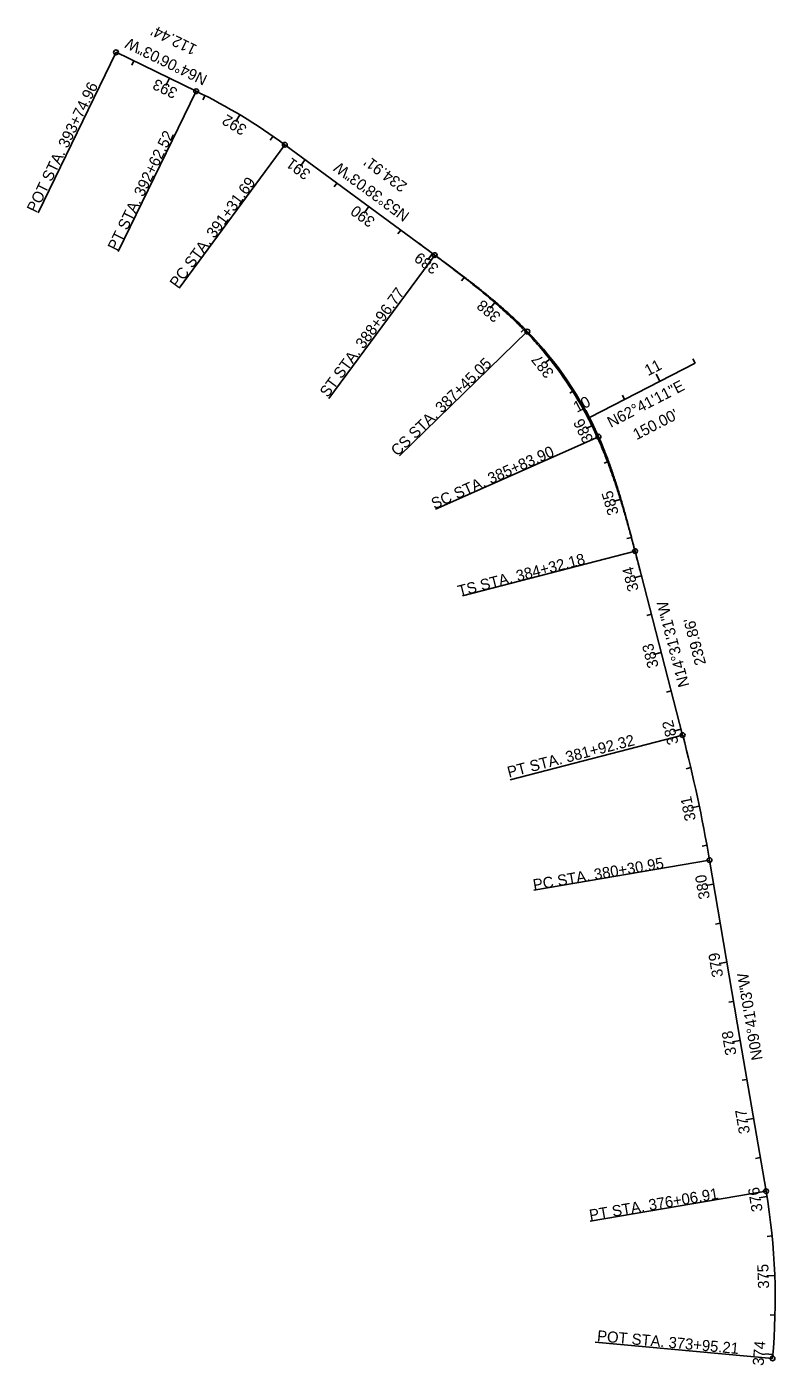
# Model space of a CAD drawing. Extents: x 111353 to 112297, y 429419 to 431109.
import ezdxf

# ---------------------------------------------------------------- set-up
doc = ezdxf.new("R2010")
doc.units = 0
for name, color, linetype in [('DR_P_Headwall', 7, 'Continuous'), ('DT_X_Island', 7, 'Continuous'), ('DT_X_Terrain_Boundary', 7, 'Continuous'), ('GK_Drainage_Nodes', 7, 'Continuous'), ('PV_P_Shoulder', 7, 'Continuous')]:
    doc.layers.add(name, color=color, linetype=linetype)

msp = doc.modelspace()

# ---------------------------------------------------------------- linework, layer by layer
at = {"layer": 'DR_P_Headwall'}
for p, q in [((111488, 431065.5), (111485.4, 431060.1)), ((111533, 431043.7), (111528.6, 431034.7)), ((111577.9, 431021.8), (111575.2, 431016.4)), ((111621.7, 430997.6), (111616.6, 430989)), ((111663.7, 430970.4), (111660.2, 430965.5)), ((111704.1, 430941), (111698.2, 430932.9)), ((111744.3, 430911.3), (111740.8, 430906.5)), ((111784.6, 430881.7), (111778.7, 430873.6)), ((111824.9, 430852), (111821.3, 430847.2)), ((111865.1, 430822.4), (111859.2, 430814.3)), ((111905.2, 430792.6), (111901.6, 430787.8)), ((111944.3, 430761.4), (111937.9, 430753.7)), ((111981.1, 430727.6), (111976.9, 430723.4)), ((112014.4, 430690.2), (112006.5, 430684)), ((112196.2, 430684.1), (112193.4, 430689.5)), ((112151.7, 430661.2), (112147.1, 430670.1)), ((112043.3, 430649.5), (112038.2, 430646.3)), ((112107.3, 430638.3), (112104.5, 430643.6)), ((112062.9, 430615.3), (112058.3, 430624.2)), ((112067.6, 430605.8), (112058.7, 430601.5)), ((112087.2, 430559.8), (112081.5, 430557.8)), ((112102.8, 430512.3), (112093.2, 430509.5)), ((112116, 430464.1), (112110.2, 430462.6)), ((112128.6, 430415.7), (112118.9, 430413.2)), ((112141.1, 430367.3), (112135.3, 430365.8)), ((112153.6, 430318.9), (112144, 430316.4)), ((112166.2, 430270.5), (112160.4, 430269)), ((112178.7, 430222.1), (112169, 430219.6)), ((112190.8, 430173.6), (112185, 430172.2)), ((112201.6, 430124.8), (112191.8, 430122.8)), ((112211.2, 430075.7), (112205.3, 430074.6)), ((112219.7, 430026.4), (112209.8, 430024.8)), ((112228.1, 429977.2), (112222.2, 429976.1)), ((112236.5, 429927.9), (112226.6, 429926.2)), ((112244.9, 429878.6), (112239, 429877.6)), ((112253.3, 429829.3), (112243.5, 429827.6)), ((112261.7, 429780), (112255.8, 429779)), ((112270.1, 429730.7), (112260.3, 429729)), ((112278.6, 429681.4), (112272.6, 429680.4)), ((112286.9, 429632.1), (112277.1, 429630.5)), ((112293.4, 429582.6), (112287.4, 429582)), ((112296.8, 429532.7), (112286.8, 429532.3)), ((112297.2, 429482.7), (112291.2, 429482.8)), ((112294.5, 429432.8), (112284.5, 429433.6))]:
    msp.add_line(p, q, dxfattribs=at)
at = {"layer": 'DT_X_Terrain_Boundary'}
for p, q in [((111465.6, 431076.4), (111367.3, 430874)), ((111566.7, 431027.3), (111468.5, 430824.9)), ((111678.6, 430959.8), (111545.2, 430778.6)), ((111867.7, 430820.5), (111734.3, 430639.3)), ((111984.6, 430724), (111823.2, 430567.3)), ((112074.4, 430591.3), (111868.9, 430499.7)), ((112120.5, 430446.9), (111902.7, 430390.4)), ((112180.6, 430214.7), (111962.8, 430158.3)), ((112214.5, 430056.9), (111992.7, 430019.1)), ((112285.8, 429639), (112064, 429601.1)), ((112294.1, 429428), (112070, 429448.4))]:
    msp.add_line(p, q, dxfattribs=at)
for centre in [(111465.6, 431076.4), (111566.7, 431027.3), (111678.6, 430959.8), (111867.7, 430820.5), (111984.6, 430724), (112074.4, 430591.3), (112120.5, 430446.9), (112180.6, 430214.7), (112214.5, 430056.9), (112285.8, 429639), (112294.1, 429428)]:
    msp.add_circle(centre, 3, dxfattribs=at)
at = {"layer": 'PV_P_Shoulder'}
for p, q in [((111566.7, 431027.3), (111465.6, 431076.4)), ((111867.7, 430820.5), (111678.6, 430959.8)), ((112062.9, 430615.3), (112196.2, 430684.1)), ((112180.6, 430214.7), (112120.5, 430446.9)), ((112253.3, 429829.3), (112214.5, 430056.9)), ((112285.8, 429639), (112253.3, 429829.3))]:
    msp.add_line(p, q, dxfattribs=at)
for centre, radius, start, end in [((111253.8, 430383), 716.3, 53.6341, 64.099), ((111655.7, 430404.8), 458.4, 24.0078, 44.1517), ((111655.7, 430404.8), 458.4, 24.0078, 44.1517), ((111654.3, 430403.8), 458.4, 27.0878, 41.0717), ((110331.8, 429735.7), 1909.9, 9.6841, 14.5254), ((110331.8, 429735.7), 1909.9, 9.6841, 14.5254), ((110331.8, 429735.7), 1909.9, 9.6841, 14.5254), ((111482.4, 429501.9), 815, 354.8008, 9.6842)]:
    msp.add_arc(centre, radius, start, end, dxfattribs=at)
for points in [[(111999.9, 430705), (111998.1, 430707.1), (111994.4, 430711.3), (111986.8, 430719.5), (111977.1, 430729.5), (111965.1, 430741.2), (111952.8, 430752.5), (111940.2, 430763.6), (111927.4, 430774.4), (111914.3, 430784.9), (111901.2, 430795.2), (111887.9, 430805.4), (111874.5, 430815.5), (111863.2, 430823.8), (111854.3, 430830.4), (111849.8, 430833.7), (111847.5, 430835.4)], [(111984.6, 430724), (111982.9, 430725.9), (111979.3, 430729.5), (111972.1, 430736.5), (111962.9, 430745.2), (111951.5, 430755.3), (111940, 430765.1), (111928.2, 430774.7), (111916.3, 430784.1), (111904.3, 430793.3), (111892.1, 430802.5), (111882, 430810), (111873.8, 430816), (111869.8, 430819), (111867.7, 430820.5)], [(111984.6, 430724), (111982.9, 430725.9), (111979.3, 430729.5), (111972.1, 430736.5), (111962.9, 430745.2), (111951.5, 430755.3), (111940, 430765.1), (111928.2, 430774.7), (111916.3, 430784.1), (111904.3, 430793.3), (111892.1, 430802.5), (111882, 430810), (111873.8, 430816), (111869.8, 430819), (111867.7, 430820.5)], [(112126.8, 430422.6), (112126.1, 430425.3), (112124.7, 430430.7), (112121.9, 430441.5), (112118.3, 430455), (112114, 430471.2), (112109.5, 430487.3), (112104.8, 430503.4), (112099.9, 430519.4), (112094.6, 430535.3), (112089.1, 430551.1), (112083.1, 430566.8), (112076.7, 430582.3), (112071, 430595), (112066.2, 430605.1), (112063.7, 430610.1), (112062.4, 430612.5)], [(112120.5, 430446.9), (112119.9, 430449.3), (112118.6, 430454.2), (112116, 430464), (112112.8, 430476.2), (112108.9, 430490.9), (112104.8, 430505.5), (112100.5, 430520.1), (112096, 430534.5), (112091.1, 430548.9), (112086, 430563.2), (112081.4, 430575), (112077.5, 430584.3), (112075.5, 430588.9), (112074.4, 430591.3)], [(112120.5, 430446.9), (112119.9, 430449.3), (112118.6, 430454.2), (112116, 430464), (112112.8, 430476.2), (112108.9, 430490.9), (112104.8, 430505.5), (112100.5, 430520.1), (112096, 430534.5), (112091.1, 430548.9), (112086, 430563.2), (112081.4, 430575), (112077.5, 430584.3), (112075.5, 430588.9), (112074.4, 430591.3)]]:
    msp.add_open_spline(points, degree=3, dxfattribs=at)

# ---------------------------------------------------------------- texts
at = {"layer": 'DR_P_Headwall'}
for s, rotation, p in [('393', 154.1008, (111544.5, 431029.8)), ('392', 149.0985, (111631.9, 430982.7)), ('391', 143.6341, (111712.3, 430925.6)), ('390', 143.6341, (111793.6, 430865.7)), ('389', 143.6341, (111874, 430806.5)), ('388', 139.7763, (111952.2, 430744.9)), ('387', 128.5201, (112019.1, 430672.2)), ('11', 27.3136, (112137, 430667.6)), ('10', 27.3136, (112047.2, 430621.3)), ('386', 116.0202, (112068.3, 430587.5)), ('385', 106.4201, (112100.2, 430494.4)), ('384', 104.5254, (112125.4, 430398)), ('383', 104.5254, (112150.5, 430301.2)), ('382', 104.5254, (112175.6, 430204.4)), ('381', 101.7558, (112197.5, 430107.8)), ('380', 99.6841, (112215.1, 430008.7)), ('379', 99.6841, (112231.9, 429910.2)), ('378', 99.6841, (112248.7, 429811.6)), ('377', 99.6841, (112265.7, 429712.6)), ('376', 99.1984, (112281.7, 429614.1)), ('375', 92.1681, (112289.8, 429516.2)), ('374', 85.1379, (112282.7, 429418.3))]:
    msp.add_text(s, height=14, rotation=rotation, dxfattribs=at).set_placement(p)
at = {"layer": 'DT_X_Island'}
for s, rotation, p in [('N64°06\'03"W', 154.1008, (111582, 431046.6)), ('N53°38\'03"W', 143.6341, (111837, 430872.9)), ('N62°41\'11"E', 27.3136, (112090, 430602.3)), ('N14°31\'31"W', 104.5254, (112189.2, 430277.2)), ('N09°41\'03"W', 99.6841, (112281.7, 429805.5))]:
    msp.add_text(s, height=14, rotation=rotation, dxfattribs=at).set_placement(p)
at = {"layer": 'DT_X_Terrain_Boundary'}
for s, rotation, p in [('POT STA. 393+74.96', 64.1008, (111364.9, 430873)), ('PT STA. 392+62.52', 64.1008, (111466.9, 430824.8)), ('PC STA. 391+31.69', 53.6341, (111543.4, 430777.8)), ('ST STA. 388+96.77', 53.6341, (111732.8, 430640)), ('CS STA. 387+45.05', 44.1517, (111820.7, 430565.9)), ('SC STA. 385+83.90', 24.0078, (111867.2, 430499.5)), ('TS STA. 384+32.18', 14.5254, (111898.9, 430389.4)), ('PT STA. 381+92.32', 14.5254, (111961.4, 430160.8)), ('PC STA. 380+30.95', 9.6841, (111993, 430018.6)), ('PT STA. 376+06.91', 9.6841, (112064, 429601.7)), ('POT STA. 373+95.21', 354.8008, (112072.2, 429449.7))]:
    msp.add_text(s, height=14, rotation=rotation, dxfattribs=at).set_placement(p)
at = {"layer": 'GK_Drainage_Nodes'}
for s, rotation, p in [("112.44'", 154.1008, (111568.9, 431084.7)), ("234.91'", 143.6341, (111834.1, 430910)), ("150.00'", 27.3136, (112122.4, 430586.8)), ("239.86'", 104.5254, (112210.2, 430304.7))]:
    msp.add_text(s, height=14, rotation=rotation, dxfattribs=at).set_placement(p)

doc.saveas('drawing.dxf')
